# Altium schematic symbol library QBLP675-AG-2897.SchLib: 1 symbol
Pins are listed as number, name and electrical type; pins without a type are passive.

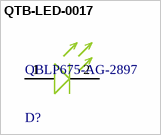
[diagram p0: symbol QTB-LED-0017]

## QTB-LED-0017
designator D?, comment QBLP675-AG-2897
LED YELLOW/GREEN CLEAR 2PLCC SMD; Manufacturer: QT Brightek (QTB); Luminous Intensity: 65mcd; Test Current: 20mA; Lens Color: Colorless; Lens Style: Oval with Flat Top; Forward Voltage: 2.0V; Wavelength - Dominant: 573nm; Viewing Angle: 120°
footprint QBLP675-AG-2897
pins: 1 ANODE (+), 2 CATHODE (-)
